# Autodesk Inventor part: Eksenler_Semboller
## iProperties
Created: 2006-02
Part Number: Eksenler_Semboller
Document SubType Name: Modeling
Designer: Administrator
Density: 1 g/cm^3
Author: Administrator
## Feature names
1. Extrusion1
2. Extrusion2
3. Fillet1
4. Chamfer1
5. Hole1
6. Chamfer3
7. Fillet2
8. Fillet3
9. Hole2
10. Chamfer4
11. Hole3
12. Chamfer5
